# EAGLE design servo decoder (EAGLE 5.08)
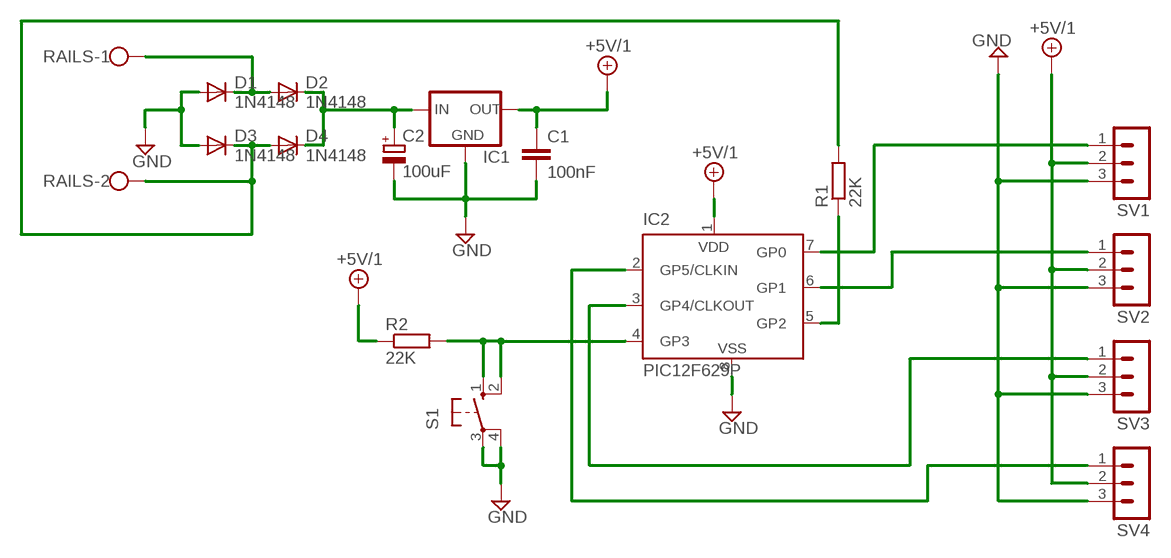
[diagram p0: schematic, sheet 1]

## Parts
C1  100nF  C-EU025-024X044  [C025-024X044]
C2  100uF  CPOL-EUE2.5-5  [E2,5-5]
D1  1N4148  1N4148DO35-10  [DO35-10]
D2  1N4148  1N4148DO35-10  [DO35-10]
D3  1N4148  1N4148DO35-10  [DO35-10]
D4  1N4148  1N4148DO35-10  [DO35-10]
IC1  78XXS  [78XXS]
IC2  PIC12F629P  [DIL8]
R1  22K  R-EU_0207/12  [0207/12]
R2  22K  R-EU_0207/12  [0207/12]
RAILS  W237-102  [W237-102]
S1  10-XX  [B3F-10XX]
SV1  MA03-1  [MA03-1]
SV2  MA03-1  [MA03-1]
SV3  MA03-1  [MA03-1]
SV4  MA03-1  [MA03-1]

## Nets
+5V/1: C1.1 IC1.OUT IC2.1(VDD) R2.1 SV1.2 SV2.2 SV3.2 SV4.2
GND: C1.2 C2.- D1.A D3.A IC1.GND IC2.8(VSS) S1.3(P) S1.4(P1) SV1.3 SV2.3 SV3.3 SV4.3
N$1: D1.C D2.A RAILS.1
N$2: D3.C D4.A R1.2 RAILS.2
N$4: C2.+ D2.C D4.C IC1.IN
N$5: IC2.7(GP0) SV1.1
N$6: IC2.6(GP1) SV2.1
N$7: IC2.3(GP4/CLKOUT) SV3.1
N$8: IC2.2(GP5/CLKIN) SV4.1
N$9: IC2.5(GP2) R1.1
N$10: IC2.4(GP3) R2.2 S1.1(S) S1.2(S1)

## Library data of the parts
C1 = rcl:C-EU: CAPACITOR, European symbol
C2 = resistor:CPOL-EU: POLARIZED CAPACITOR, European symbol
D1-D4 = diode:1N4148: DIODE
IC1 = v-reg:78XXS: VOLTAGE REGULATOR
IC2 = microchip:PIC12F6*: Data Sheet 8-Pin FLASH-Based 8-Bit CMOS Microcontrollers Source: http://www.microchip.com .. 41190c.pdf
R1 R2 = rcl:R-EU_: RESISTOR, European symbol
RAILS = con-wago-500:W237-102: WAGO SCREW CLAMP
S1 = switch-omron:10-XX: OMRON SWITCH
SV1-SV4 = con-lstb:MA03-1: PIN HEADER

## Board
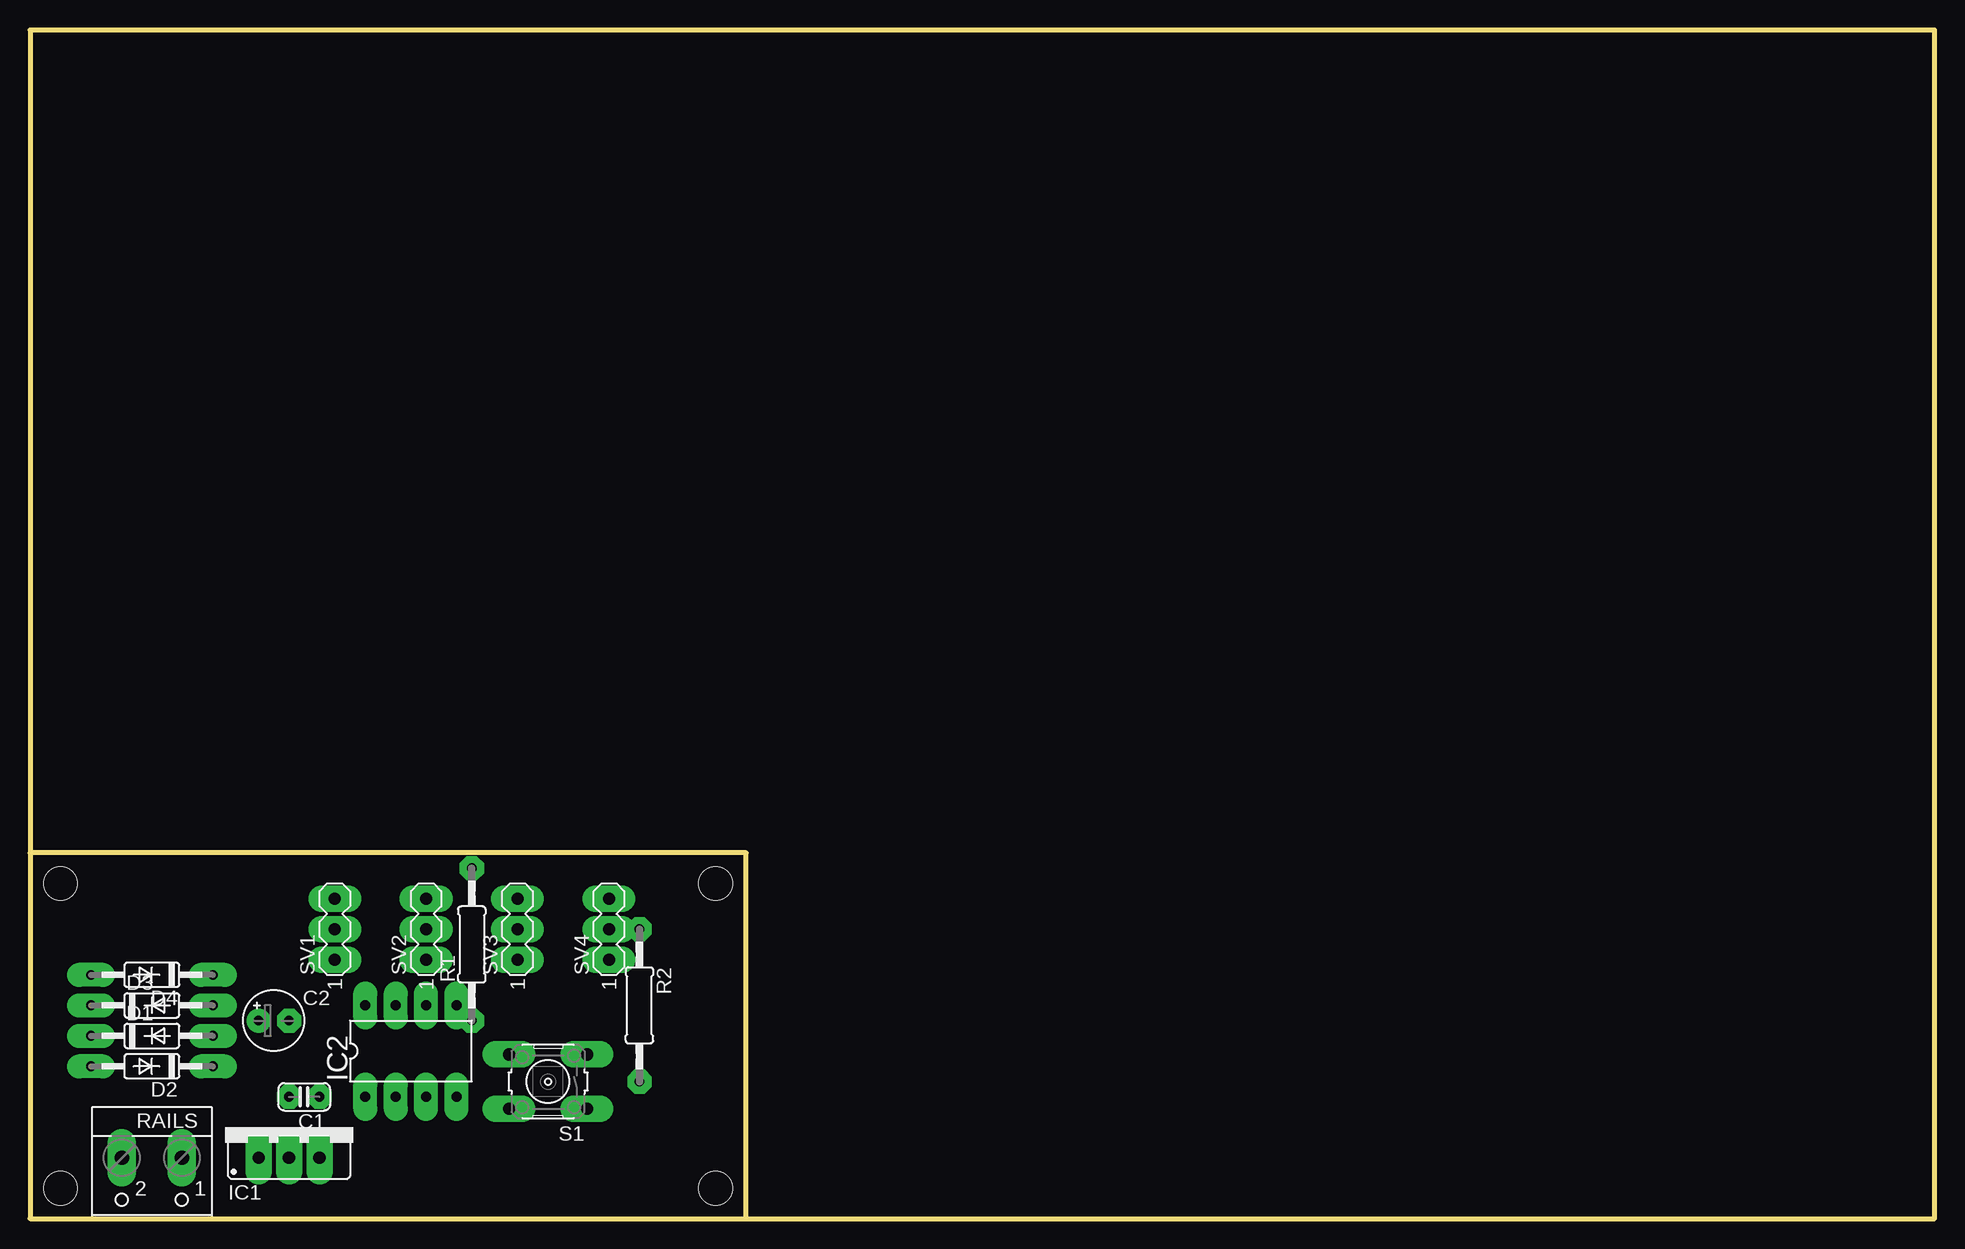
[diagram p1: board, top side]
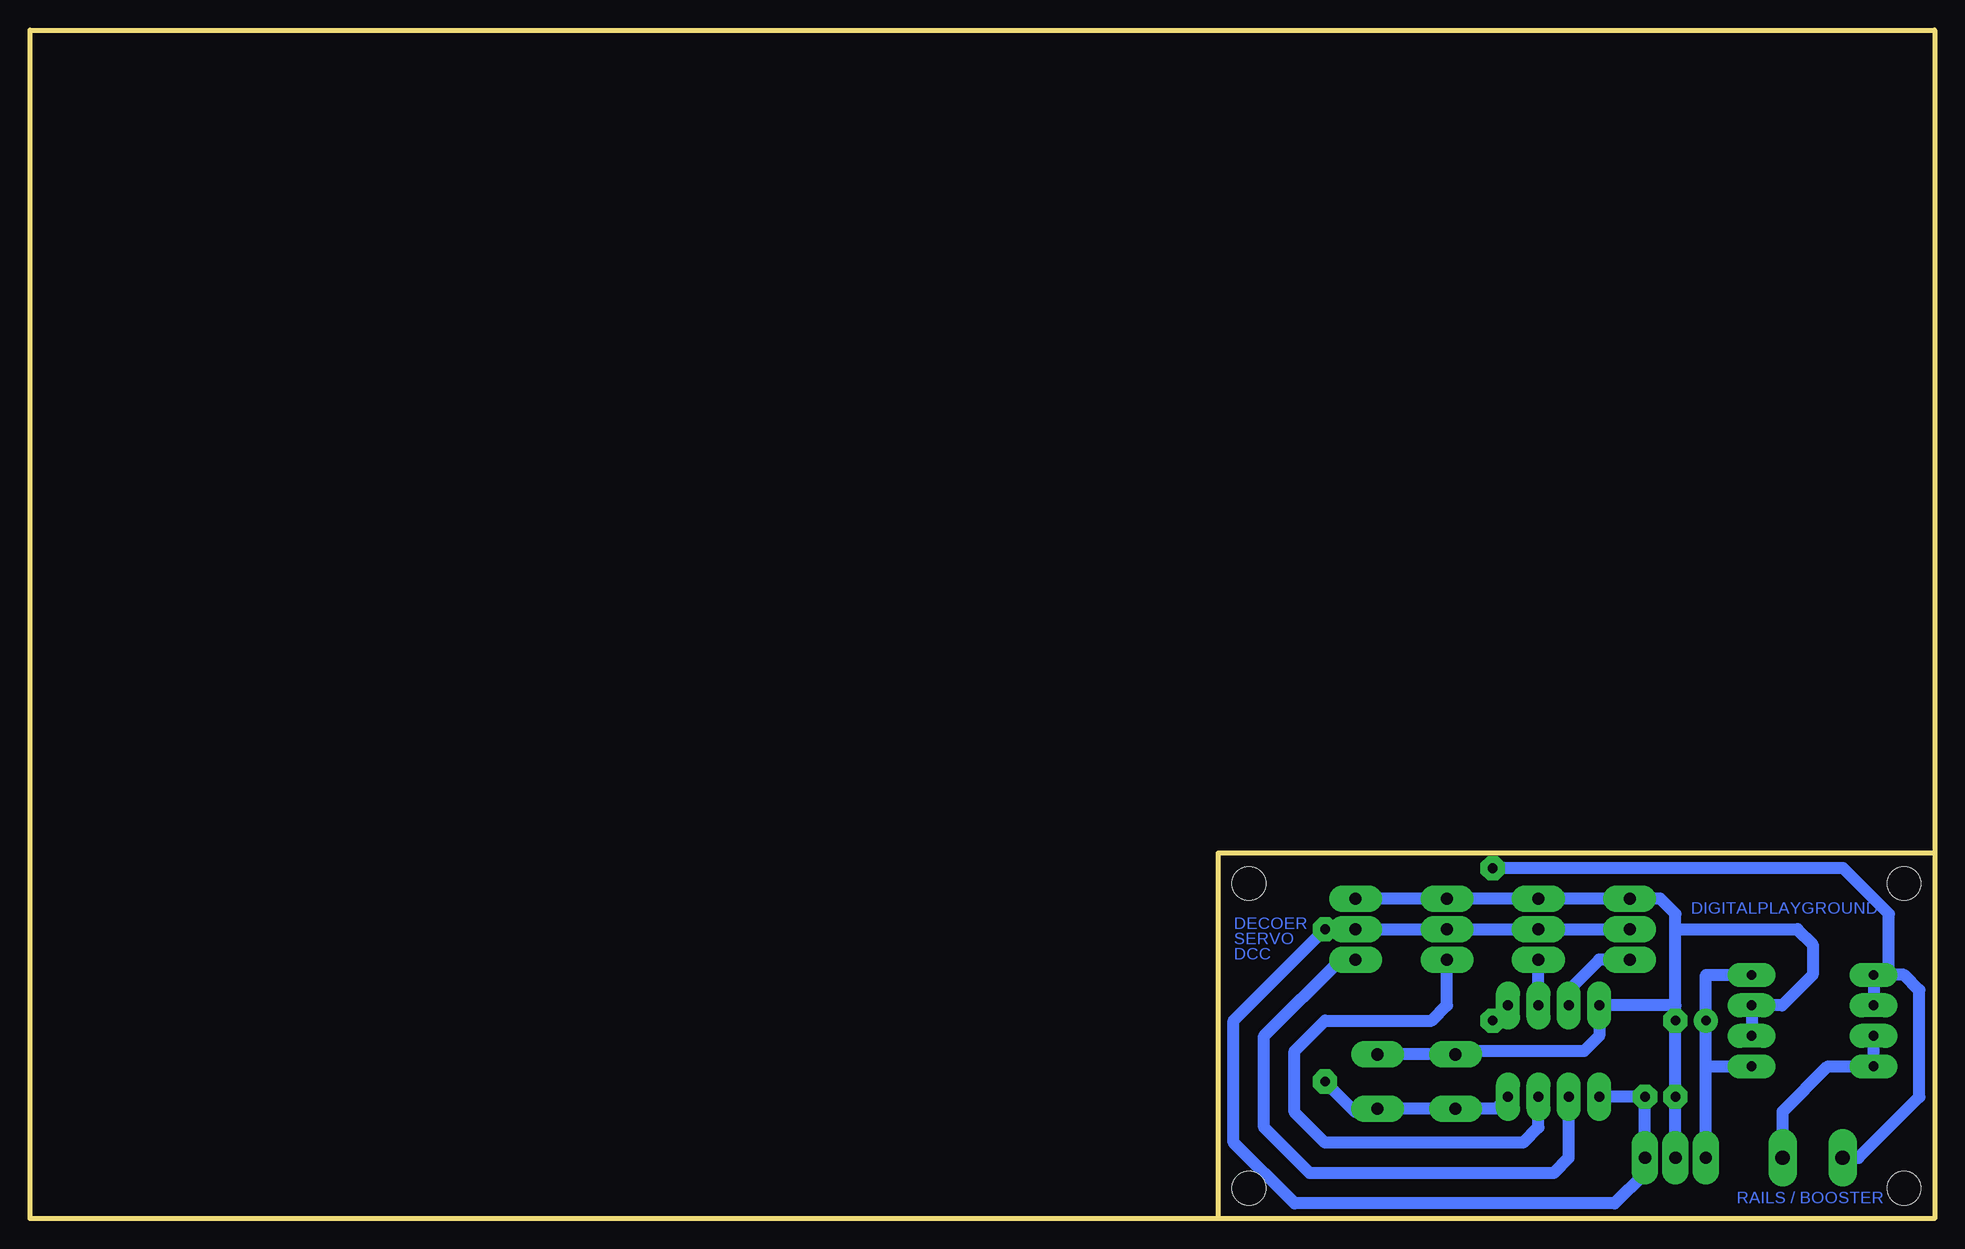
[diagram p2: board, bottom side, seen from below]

Size 158.75 x 99.06 mm. Coordinates in mm from the lower left corner, seen from the top.
Outline: 59.69,0 0,0 0,30.48
Outline: 59.69,0 158.75,0 158.75,99.06 0,99.06 0,30.48
Outline: 59.69,0 59.69,30.48 0,30.48
Copper layers (1*16): Top 1mm / dielectric 1.5mm / Bottom 1mm
Design rules "DRC settings middle": minimum track width 1.2mm, minimum drill 24mil, track to track 0.4mm, track to pad 0.4mm, pad to pad 0.4mm, via to via 0.4mm, smd to smd 8mil, copper to edge 0.5mm, drill to drill 0.5mm, minimum pad ring 0.6mm, minimum via ring 1mm, stop-mask expansion 4mil, vias tented up to drill 0mil, thermal gap 10mil
Holes 2.8 mm at 2.54,27.94 57.15,27.94 57.15,2.54 2.54,2.54

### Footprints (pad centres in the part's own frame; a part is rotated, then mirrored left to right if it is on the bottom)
C025-024X044 = drill 0.813 octagon: 1 -1.27,0; 2 1.27,0
E2,5-5 = drill 0.813 pad 1.6 round: + -1.27,0 | drill 0.813 pad 1.6 octagon: - 1.27,0
DO35-10 = drill 0.813 long: A 5.08,0; C -5.08,0
78XXS = drill 1.016 long: GND 0,-2.54; IN -2.54,-2.54; OUT 2.54,-2.54
DIL8 = drill 0.813 long: 1 -3.81,-3.81; 2 -1.27,-3.81; 3 1.27,-3.81; 4 3.81,-3.81; 5 3.81,3.81; 6 1.27,3.81; 7 -1.27,3.81; 8 -3.81,3.81
0207/12 = drill 0.813 octagon: 1 -6.35,0; 2 6.35,0
W237-102 = drill 1.194 long: 1 -2.5,-1.27; 2 2.5,-1.27
B3F-10XX = drill 1.016 long: 1 -3.251,2.261; 2 3.251,2.261; 3 -3.251,-2.261; 4 3.251,-2.261
MA03-1 = drill 1.016 long: 1 -2.54,0; 2 0,0; 3 2.54,0

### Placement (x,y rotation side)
C1  22.86,10.16 180 top
C2  20.32,16.51 0 top
D1  10.16,15.24 0 top
D2  10.16,12.7 180 top
D3  10.16,17.78 0 top
D4  10.16,20.32 180 top
IC1  21.59,7.62 0 top
IC2  31.75,13.97 0 top
R1  36.83,22.86 90 top
R2  50.8,17.78 270 top
RAILS  10.16,3.81 180 top
S1  43.18,11.43 180 top
SV1  25.4,24.13 90 top
SV2  33.02,24.13 90 top
SV3  40.64,24.13 90 top
SV4  48.26,24.13 90 top

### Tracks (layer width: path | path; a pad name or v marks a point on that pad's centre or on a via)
+5V/1
  Bottom 1.016: IC2.1 C1.1 IC1.OUT 24.13,3.81 26.67,1.27 53.34,1.27 58.42,6.35 58.42,16.51 R2.1 SV4.2 SV3.2 SV2.2 SV1.2
GND
  Bottom 1.016: S1.3 S1.4 39.65,13.97 29.21,13.97 27.94,15.24 IC2.8 21.59,17.78 | IC1.GND C1.2 C2.- 21.59,17.78 | SV4.3 SV3.3 SV2.3 SV1.3 22.86,26.67 21.59,25.4 21.59,24.13 | 21.59,17.78 21.59,24.13 | D1.A D3.A 12.7,17.78 10.16,20.32 10.16,22.86 11.43,24.13 21.59,24.13
N$1
  Bottom 1.016: D1.C D2.A 8.89,12.7 12.66,8.93 RAILS.1
N$2
  Bottom 1.016: R1.2 7.62,29.21 3.81,25.4 3.81,20.32 | RAILS.2 6.35,5.08 1.27,10.16 1.27,19.05 2.54,20.32 3.81,20.32 | 3.81,20.32 D4.A D3.C
N$4
  Bottom 1.016: IC1.IN 19.05,12.7 | 19.05,12.7 C2.+ 19.05,20.32 D4.C | 19.05,12.7 D2.C
N$5
  Bottom 1.016: IC2.7 30.48,19.05 27.94,21.59 SV1.1
N$6
  Bottom 1.016: IC2.6 SV2.1
N$7
  Bottom 1.016: IC2.3 33.02,7.62 34.29,6.35 50.8,6.35 53.34,8.89 53.34,13.97 50.8,16.51 41.91,16.51 40.64,17.78 SV3.1
N$8
  Bottom 1.016: IC2.2 30.48,5.08 31.75,3.81 52.07,3.81 55.88,7.62 55.88,15.24 49.53,21.59 SV4.1
N$9
  Bottom 1.016: R1.1 IC2.5
N$10
  Bottom 1.016: IC2.4 36.55,9.17 S1.2 S1.1 46.71,8.89 48.26,8.89 R2.2

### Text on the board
Bottom: DIGITALPLAYGROUND | DECOER | SERVO | DCC | RAILS / BOOSTER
